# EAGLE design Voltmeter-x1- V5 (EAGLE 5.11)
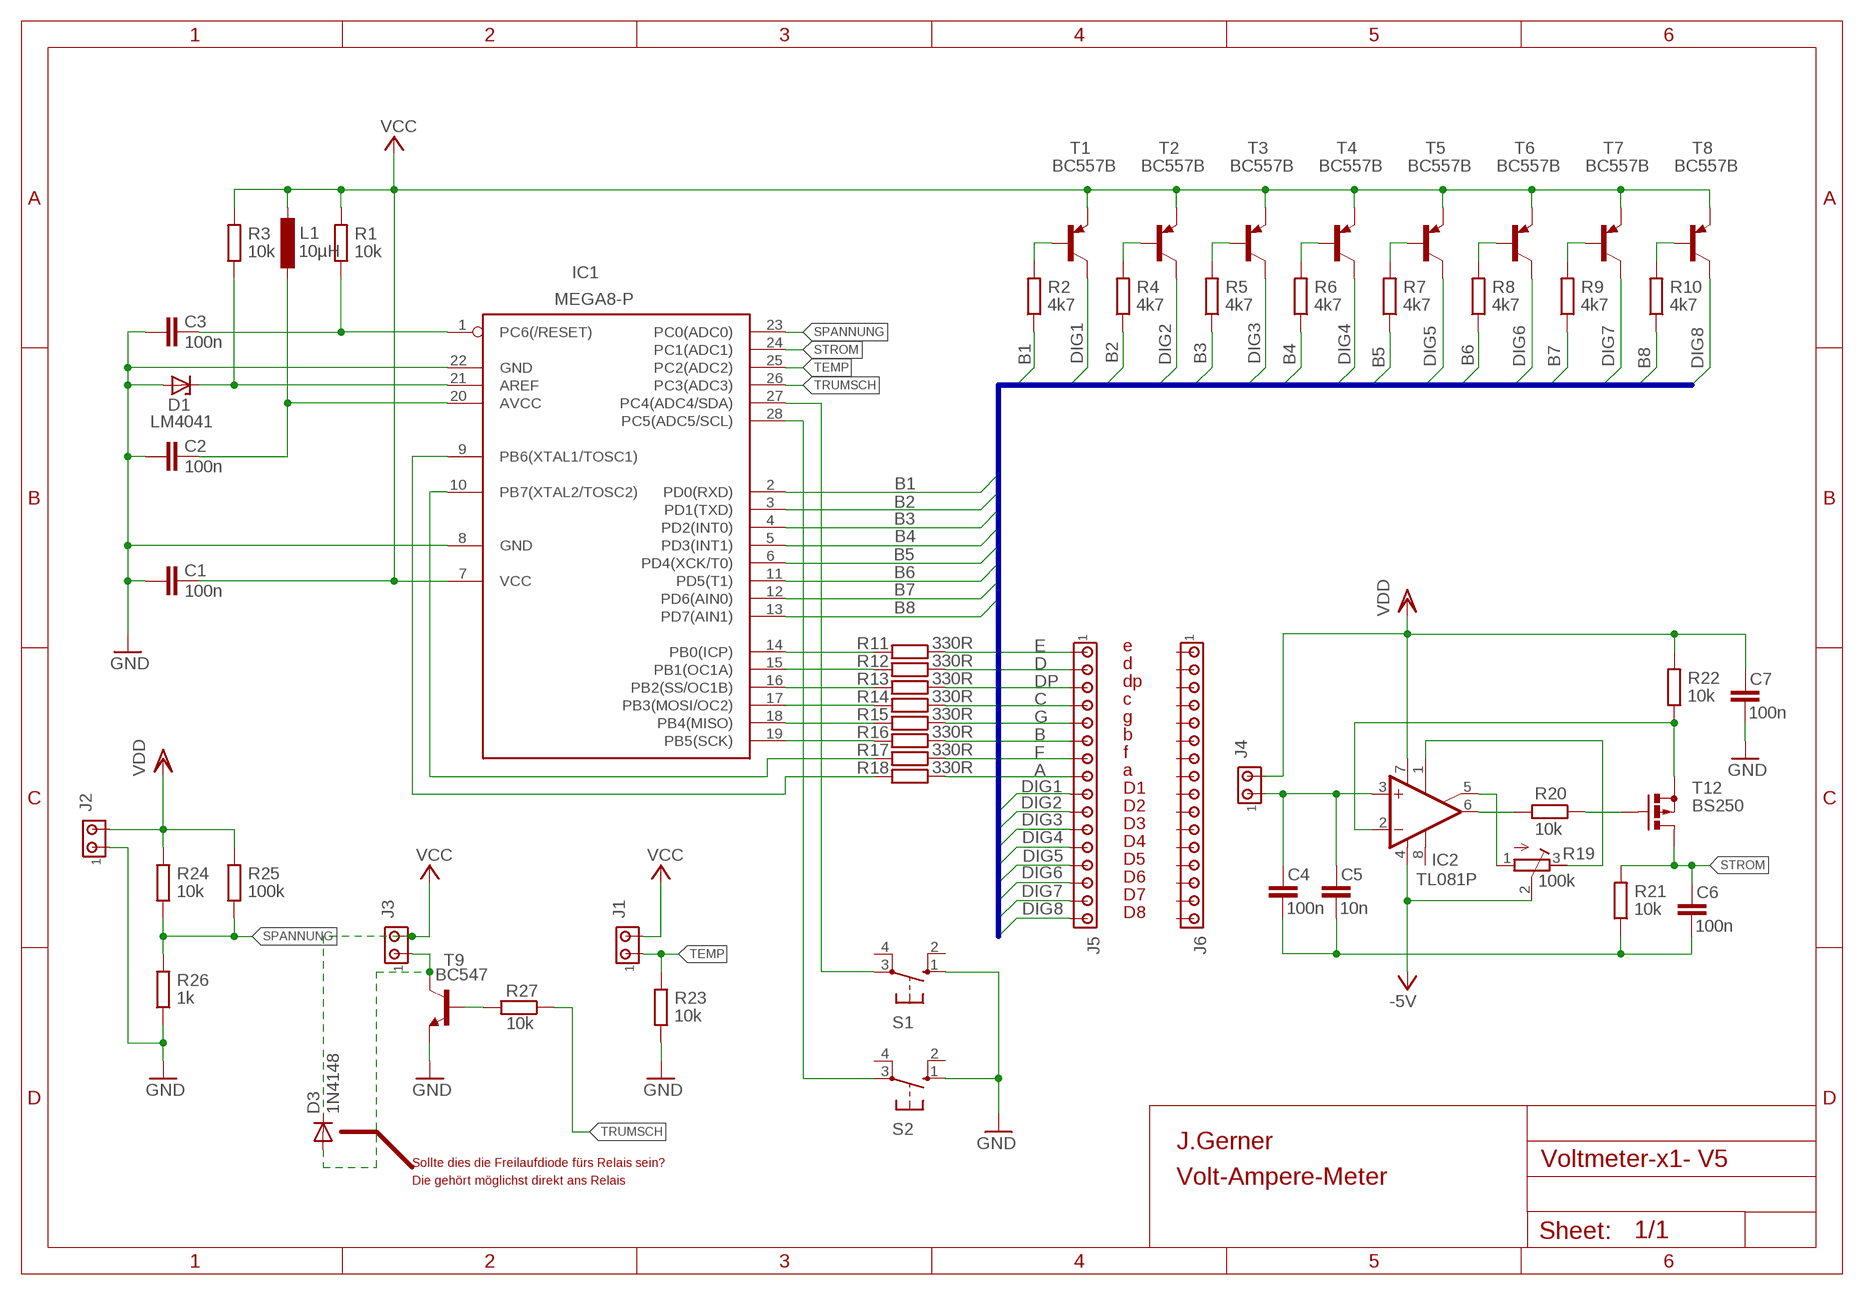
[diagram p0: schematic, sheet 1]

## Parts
C1  100n  C-EUC0805K  [C0805K]
C2  100n  C-EUC0805K  [C0805K]
C3  100n  C-EUC0805K  [C0805K]
C4  100n  C-EUC0805K  [C0805K]
C5  10n  C-EUC0805K  [C0805K]
C6  100n  C-EUC0805K  [C0805K]
C7  100n  C-EUC0805K  [C0805K]
D1  LM4041  1N4728  [DO41Z10]
D3  1N4148  1N4148DO35-7  [DO35-7]
IC1  MEGA8-P  [DIL28-3]
IC2  TL081P  [DIL08]
J1  MTA02-100  [10X02MTA]
J2  MTA02-100  [10X02MTA]
J3  MTA02-100  [10X02MTA]
J4  MTA02-100  [10X02MTA]
J5  MTA16-156  [1X16MTA]
J6  MTA16-156  [1X16MTA]
L1  10µH  L-EU0204V  [0204V]
R1  10k  R-EU_0204/2V  [0204V]
R2  4k7  R-EU_0204/2V  [0204V]
R3  10k  R-EU_0204/2V  [0204V]
R4  4k7  R-EU_0204/2V  [0204V]
R5  4k7  R-EU_0204/2V  [0204V]
R6  4k7  R-EU_0204/2V  [0204V]
R7  4k7  R-EU_0204/2V  [0204V]
R8  4k7  R-EU_0204/2V  [0204V]
R9  4k7  R-EU_0204/2V  [0204V]
R10  4k7  R-EU_0204/2V  [0204V]
R11  330R  R-EU_0204/2V  [0204V]
R12  330R  R-EU_0204/2V  [0204V]
R13  330R  R-EU_0204/2V  [0204V]
R14  330R  R-EU_0204/2V  [0204V]
R15  330R  R-EU_0204/2V  [0204V]
R16  330R  R-EU_0204/2V  [0204V]
R17  330R  R-EU_0204/2V  [0204V]
R18  330R  R-EU_0204/2V  [0204V]
R19  100k  R-TRIMM3296Y  [RTRIM3296Y]
R20  10k  R-EU_0204/2V  [0204V]
R21  10k  R-EU_0204/2V  [0204V]
R22  10k  R-EU_0204/2V  [0204V]
R23  10k  R-EU_0204/2V  [0204V]
R24  10k  R-EU_0204/2V  [0204V]
R25  100k  R-EU_0204/2V  [0204V]
R26  1k  R-EU_0204/2V  [0204V]
R27  10k  R-EU_0207/10  [0207/10]
S1  10-XX  [B3F-10XX]
S2  10-XX  [B3F-10XX]
T1  BC557B  [TO92-EBC]
T2  BC557B  [TO92-EBC]
T3  BC557B  [TO92-EBC]
T4  BC557B  [TO92-EBC]
T5  BC557B  [TO92-EBC]
T6  BC557B  [TO92-EBC]
T7  BC557B  [TO92-EBC]
T8  BC557B  [TO92-EBC]
T9  BC547  BC547B-NPN-TO92-CBE  [TO92-CBE]
T12  BS250  [SOT54E]

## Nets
-5V: IC2.4(V-) R19.2(S)
A: J5.8 R18.1
B: J5.6 R16.1
B1: IC1.2(PD0(RXD)) R2.1
B2: IC1.3(PD1(TXD)) R4.1
B3: IC1.4(PD2(INT0)) R5.1
B4: IC1.5(PD3(INT1)) R6.1
B5: IC1.6(PD4(XCK/T0)) R7.1
B6: IC1.11(PD5(T1)) R8.1
B7: IC1.12(PD6(AIN0)) R9.1
B8: IC1.13(PD7(AIN1)) R10.1
C: J5.4 R14.1
D: J5.2 R12.1
DIG1: J5.9 T1.C
DIG2: J5.10 T2.C
DIG3: J5.11 T3.C
DIG4: J5.12 T4.C
DIG5: J5.13 T5.C
DIG6: J5.14 T6.C
DIG7: J5.15 T7.C
DIG8: J5.16 T8.C
DP: J5.3 R13.1
E: J5.1 R11.1
F: J5.7 R17.1
G: J5.5 R15.1
GND: C1.2 C2.2 C3.2 C7.2 D1.A IC1.8(GND) IC1.22(GND) J2.1 R23.1 R26.1 S1.1(S) S2.1(S) T9.E
N$1: C3.1 IC1.1(PC6(/RESET)) R1.1
N$2: IC1.10(PB7(XTAL2/TOSC2)) R17.2
N$3: D1.C IC1.21(AREF) R3.1
N$4: C2.1 IC1.20(AVCC) L1.2
N$5: IC1.9(PB6(XTAL1/TOSC1)) R18.2
N$6: R2.2 T1.B
N$7: R4.2 T2.B
N$8: IC1.14(PB0(ICP)) R11.2
N$9: R5.2 T3.B
N$10: IC1.15(PB1(OC1A)) R12.2
N$11: R6.2 T4.B
N$12: IC1.16(PB2(SS/OC1B)) R13.2
N$13: R7.2 T5.B
N$14: IC1.17(PB3(MOSI/OC2)) R14.2
N$15: R8.2 T6.B
N$16: IC1.18(PB4(MISO)) R15.2
N$17: IC1.19(PB5(SCK)) R16.2
N$18: R9.2 T7.B
N$19: IC2.6(OUT) R20.2
N$20: R10.2 T8.B
N$21: R20.1 T12.G
N$22: IC2.5(ON2) R19.1(A)
N$23: IC2.1(ON1) R19.3(E)
N$24: IC2.2(-IN) R22.1 T12.S
N$25: C4.1 C5.1 IC2.3(+IN) J4.1
N$26: C4.2 C5.2 C6.2 R21.1
N$27: D3.A J3.1 T9.C
N$28: R27.2 T9.B
N$30: IC1.28(PC5(ADC5/SCL)) S2.3(P)
N$31: IC1.27(PC4(ADC4/SDA)) S1.3(P)
SPANNUNG: IC1.23(PC0(ADC0)) R24.1 R25.1 R26.2
STROM: C6.1 IC1.24(PC1(ADC1)) R21.2 T12.D
TEMP: IC1.25(PC2(ADC2)) J1.1 R23.2
TRUMSCH: IC1.26(PC3(ADC3)) R27.1
VCC: C1.1 D3.C IC1.7(VCC) J1.2 J3.2 L1.1 R1.2 R3.2 T1.E T2.E T3.E T4.E T5.E T6.E T7.E T8.E
VDD: C7.1 IC2.7(V+) J2.2 J4.2 R22.2 R24.2 R25.2
Unconnected: IC2.8(OPT) J6.1 J6.2 J6.3 J6.4 J6.5 J6.6 J6.7 J6.8 J6.9 J6.10 J6.11 J6.12 J6.13 J6.14 J6.15 J6.16 S1.2(S1) S1.4(P1) S2.2(S1) S2.4(P1)

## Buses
B[1..8],DIG[1..8]

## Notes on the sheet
- e
- d
- dp
- c
- g
- b
- f
- a
- D1
- D2
- D3
- D4
- D5
- D6
- D7
- D8
- J.Gerner
- Sollte dies die Freilaufdiode fürs Relais sein?
- Die gehört möglichst direkt ans Relais | Volt-Ampere-Meter

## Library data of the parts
C1-C7 = rcl:C-EU: CAPACITOR, European symbol
D1 = diode:1N4728: Z DIODE
D3 = diode:1N4148: DIODE
IC1 = atmel:MEGA8-P: MICROCONTROLLER 8 Kbytes FLASH, 1 kbytes SRAM, 512 bytes EEPROM, USART, 4-channel 10 bit ADC, 2-channel 8 bit ADC Pin compatible with Atmega48, ATMega88, ATMega168 Source: avr.lbr; OC_FARNELL: unknown; OC_NEWARK: unknown
IC2 = burr-brown-JP:TL081: OP AMP
J1-J4 = con-amp:MTA02-100: AMP connector; OC_FARNELL: unknown; OC_NEWARK: unknown
J5 J6 = con-amp:MTA16-156: AMP connector; OC_FARNELL: unknown; OC_NEWARK: unknown
L1 = rcl:L-EU: INDUCTOR, European symbol
R1-R18 R20-R27 = rcl:R-EU_: RESISTOR, European symbol
R19 = rcl:R-TRIMM: Trimm resistor
S1 S2 = switch-omron:10-XX: OMRON SWITCH; MPN: B3F-1000; OC_FARNELL: 176432; OC_NEWARK: 36M3542
T1-T8 = transistor-pnp:BC557*: PNP Transistror
T9 = transistor:*-NPN-: NPN Transistror BF959 corrected 2008.03.06
T12 = transistor-small-signal:BS250: P-CHANNEL MOS FET

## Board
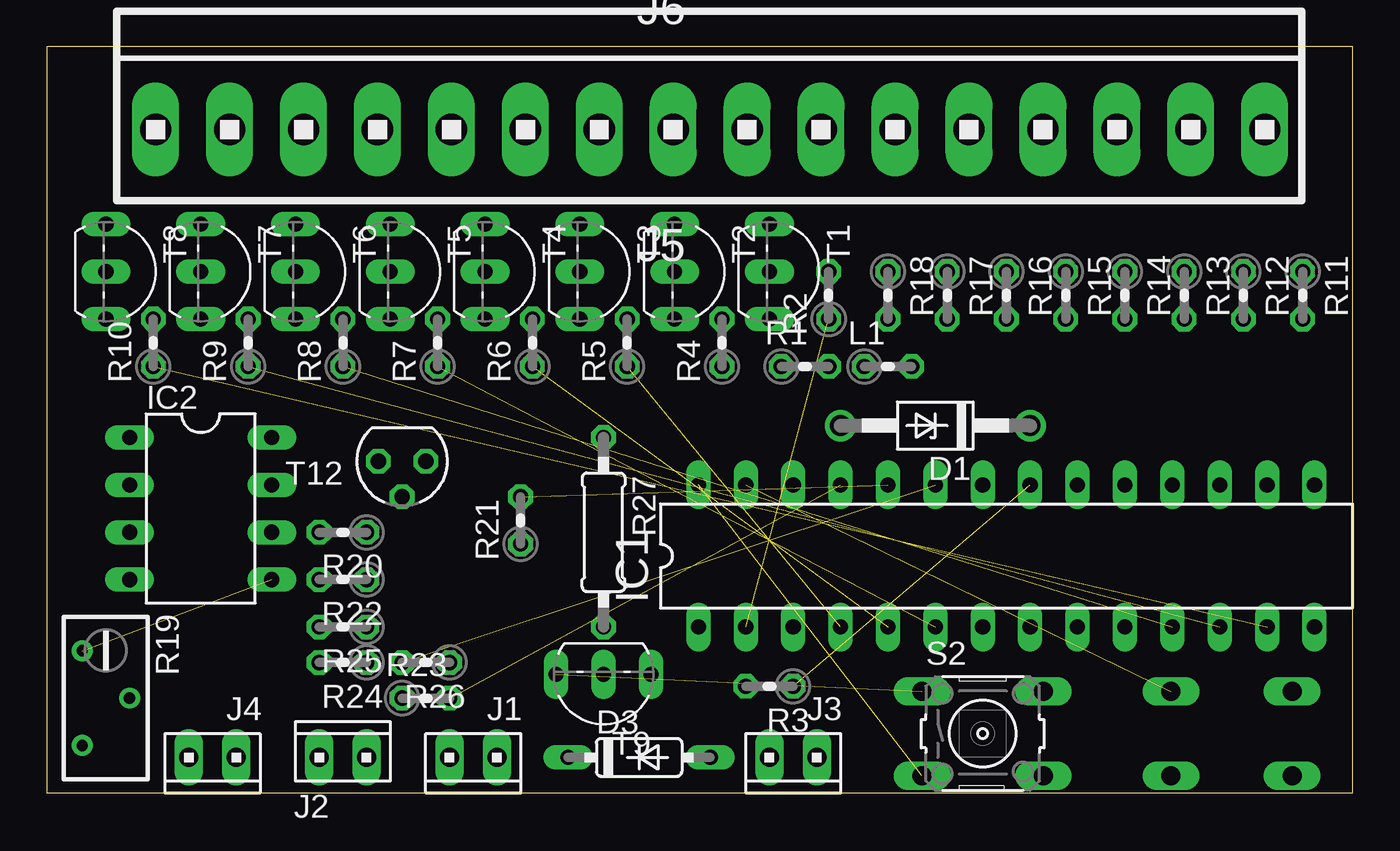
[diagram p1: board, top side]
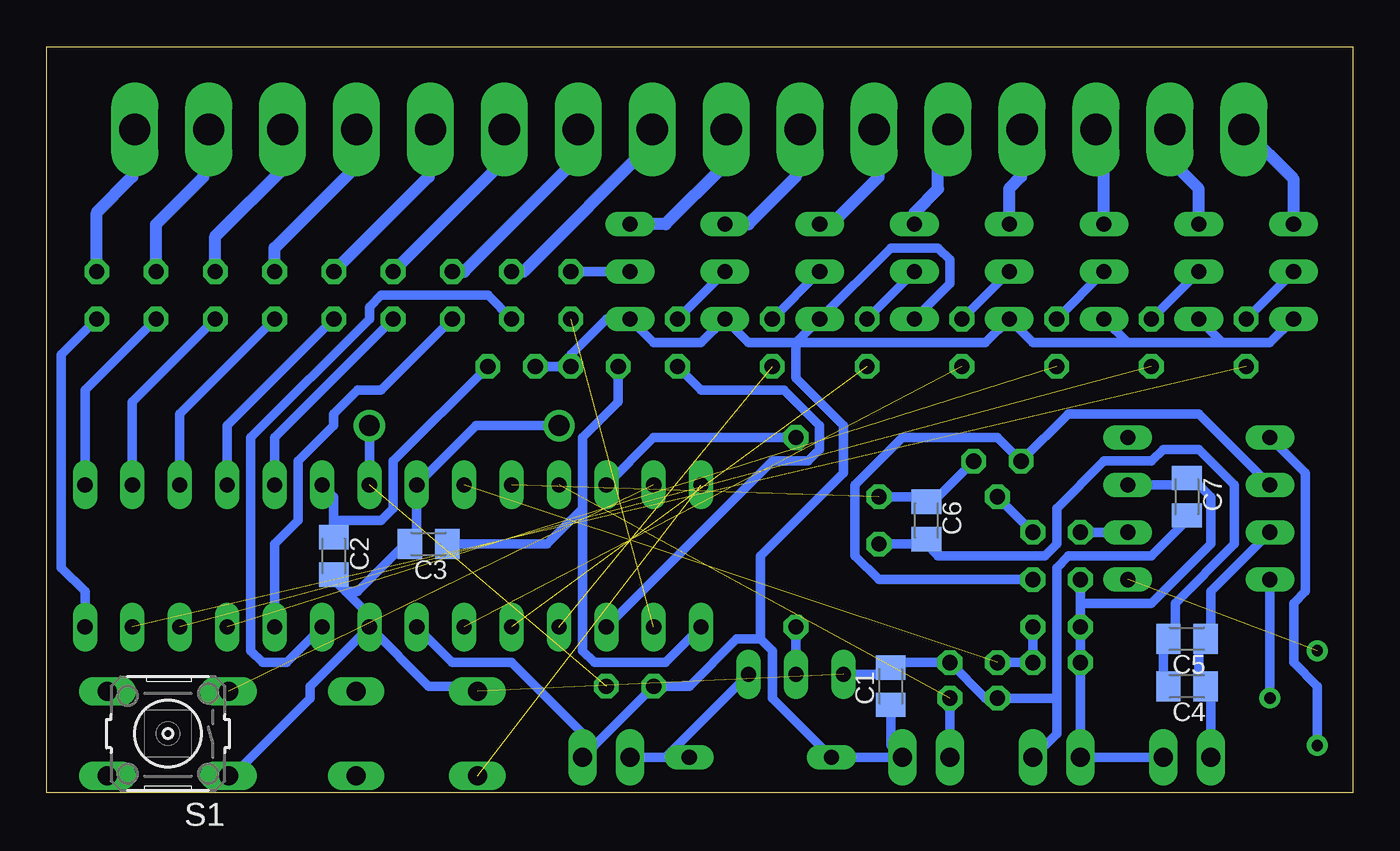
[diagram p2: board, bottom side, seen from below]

Size 70 x 40 mm. Coordinates in mm from the lower left corner, seen from the top.
Outline: 0,0 70,0 70,40 0,40 0,0
Copper layers (1*16): Top 0.035mm / dielectric 1.5mm / Bottom 0.035mm
Design rules "default *": minimum track width 20mil, minimum drill 24mil, track to track 8mil, track to pad 8mil, pad to pad 8mil, via to via 8mil, smd to smd 8mil, copper to edge 40mil, drill to drill 8mil, minimum pad ring 10mil, minimum via ring 8mil, stop-mask expansion 4mil, vias tented up to drill 0mil, thermal gap 10mil

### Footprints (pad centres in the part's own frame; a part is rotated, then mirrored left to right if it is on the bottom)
C0805K = smd 1.3 x 1.6: 1 -1,0; 2 1,0
DO41Z10 = drill 1.118 round: A 5.08,0; C -5.08,0
DO35-7 = drill 0.813 long: A 3.81,0; C -3.81,0
DIL28-3 = drill 0.813 long: 1 -16.51,-3.81; 2 -13.97,-3.81; 3 -11.43,-3.81; 4 -8.89,-3.81; 5 -6.35,-3.81; 6 -3.81,-3.81; 7 -1.27,-3.81; 8 1.27,-3.81; 9 3.81,-3.81; 10 6.35,-3.81; 11 8.89,-3.81; 12 11.43,-3.81; 13 13.97,-3.81; 14 16.51,-3.81; 15 16.51,3.81; 16 13.97,3.81; 17 11.43,3.81; 18 8.89,3.81; 19 6.35,3.81; 20 3.81,3.81; 21 1.27,3.81; 22 -1.27,3.81; 23 -3.81,3.81; 24 -6.35,3.81; 25 -8.89,3.81; 26 -11.43,3.81; 27 -13.97,3.81; 28 -16.51,3.81
DIL08 = drill 0.813 long: 1 -3.81,-3.81; 2 -1.27,-3.81; 3 1.27,-3.81; 4 3.81,-3.81; 5 3.81,3.81; 6 1.27,3.81; 7 -1.27,3.81; 8 -3.81,3.81
10X02MTA = drill 1.016 long: 1 1.27,0; 2 -1.27,0
1X16MTA = drill 1.676 long: 1 29.718,0; 2 25.756,0; 3 21.793,0; 4 17.831,0; 5 13.868,0; 6 9.906,0; 7 5.944,0; 8 1.981,0; 9 -1.981,0; 10 -5.944,0; 11 -9.906,0; 12 -13.868,0; 13 -17.831,0; 14 -21.793,0; 15 -25.756,0; 16 -29.718,0
0204V = drill 0.813 octagon: 1 -1.27,0; 2 1.27,0
RTRIM3296Y = drill 0.61 round: 1 1.27,-2.54; 2 -1.27,0; 3 1.27,2.54
0207/10 = drill 0.813 octagon: 1 -5.08,0; 2 5.08,0
B3F-10XX = drill 1.016 long: 1 -3.251,2.261; 2 3.251,2.261; 3 -3.251,-2.261; 4 3.251,-2.261
TO92-EBC = drill 0.813 long: B 0,-1.27; C -2.54,-1.27; E 2.54,-1.27
TO92-CBE = drill 0.813 long: B 0,0; C -2.54,0; E 2.54,0
SOT54E = drill 0.813 octagon: D -1.27,0; G 0,1.905; S 1.27,0

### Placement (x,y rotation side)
C1  24.77,5.71 90 bottom
C2  54.61,12.7 270 bottom
C3  49.53,13.34 180 bottom
C4  8.89,5.71 180 bottom
C5  8.89,8.26 180 bottom
C6  22.86,14.61 270 bottom
C7  8.89,15.88 270 bottom
D1  47.62,19.68 180 top
D3  31.75,1.91 0 top
IC1  51.44,12.7 0 top
IC2  8.26,15.24 270 top
J1  22.86,1.91 180 top
J2  15.88,1.91 0 top
J3  40.01,1.91 180 top
J4  8.89,1.91 180 top
J5  35.56,35.56 0 top
J6  not placed on the board
L1  45.09,22.86 0 top
R1  40.64,22.86 0 top
R2  41.91,26.67 90 top
R3  38.73,5.71 180 top
R4  36.2,24.13 90 top
R5  31.11,24.13 90 top
R6  26.04,24.13 90 top
R7  20.95,24.13 90 top
R8  15.88,24.13 90 top
R9  10.79,24.13 90 top
R10  5.71,24.13 90 top
R11  67.31,26.67 270 top
R12  64.14,26.67 270 top
R13  60.96,26.67 270 top
R14  57.78,26.67 270 top
R15  54.61,26.67 270 top
R16  51.44,26.67 270 top
R17  48.26,26.67 270 top
R18  45.09,26.67 270 top
R19  3.17,5.08 180 top
R20  15.88,13.97 180 top
R21  25.4,14.61 90 top
R22  15.88,11.43 180 top
R23  20.32,5.08 0 top
R24  15.88,6.99 180 top
R25  15.88,8.89 180 top
R26  20.32,6.99 180 top
R27  29.84,13.97 270 top
S1  63.5,3.17 180 bottom
S2  50.16,3.17 0 top
T1  40.01,27.94 270 top
T2  34.92,27.94 270 top
T3  29.84,27.94 270 top
T4  24.77,27.94 270 top
T5  19.68,27.94 270 top
T6  14.61,27.94 270 top
T7  9.53,27.94 270 top
T8  4.45,27.94 270 top
T9  29.84,6.35 180 top
T12  19.05,17.78 180 top

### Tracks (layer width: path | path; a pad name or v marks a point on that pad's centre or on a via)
-5V
  Bottom 0.508: R19.2 IC2.4
A
  Bottom 0.635: R18.1 44.45,27.94 37.47,34.92 37.47,35.48 J5.8
B
  Bottom 0.635: R16.1 45.72,33.66 45.72,35.31 J5.6
B1  (1 unrouted)
B2
  Bottom 0.508: IC1.3 31.11,17.78 29.21,17.78 28.57,18.41 28.57,19.68 30.48,21.59 34.92,21.59 R4.1
B3  (1 unrouted)
B4  (1 unrouted)
B5  (1 unrouted)
B6  (1 unrouted)
B7  (1 unrouted)
B8  (1 unrouted)
C
  Bottom 0.635: R14.1 57.78,29.21 53.34,33.66 53.34,35.51 J5.4
D
  Bottom 0.635: R12.1 64.14,30.48 61.59,33.02 61.59,35.28 J5.2
DIG1
  Bottom 0.635: T1.C 36.83,30.48 33.66,33.66 33.66,35.48 J5.9
DIG2
  Bottom 0.635: T2.C 32.38,30.48 29.84,33.02 29.84,35.33 J5.10
DIG3
  Bottom 0.635: T3.C 27.94,30.48 25.4,33.02 25.4,35.31 J5.11
DIG4
  Bottom 0.635: T4.C 23.5,31.11 22.23,32.38 22.23,35.03 J5.12
DIG5
  Bottom 0.635: T5.C 18.41,32.38 17.78,33.02 17.78,35.51 J5.13
DIG6
  Bottom 0.635: T6.C 13.34,35.13 J5.14
DIG7
  Bottom 0.635: T7.C 8.26,32.38 9.53,33.66 9.53,35.28 J5.15
DIG8
  Bottom 0.635: T8.C 3.17,32.89 J5.16
DP
  Bottom 0.635: R13.1 60.96,29.84 57.15,33.66 57.15,35.36 J5.3
E
  Bottom 0.635: R11.1 67.31,31.11 65.41,33.02 65.41,35.43 J5.1
F
  Bottom 0.635: R17.1 47.62,27.94 41.27,34.29 41.27,35.33 J5.7
G
  Bottom 0.635: R15.1 49.53,33.02 49.53,35.46 J5.5
GND  (1 unrouted)
  Bottom 0.508: D1.A 46.99,19.68 IC1.22 50.16,13.34 C3.2 50.8,13.34 53.34,10.79 53.98,10.79 | T9.E 24.77,6.35 C1.2 24.77,6.99 R26.1 19.68,5.08 R23.1 15.88,5.08 | 15.88,5.08 15.88,3.17 J2.1 | 15.88,5.08 15.88,12.06 15.24,12.7 10.79,12.7 8.89,14.61 C7.2 | 53.98,10.79 52.7,9.53 IC1.8 | 53.98,10.79 54.61,11.43 C2.2 | IC1.8 49.53,5.71 46.99,5.71 S2.1 | IC1.8 55.88,5.71 55.88,5.08 59.69,1.27 S1.1
N$1
  Bottom 0.508: 41.27,15.24 43.18,13.34 C3.1 | 41.27,15.24 41.27,19.05 39.37,20.95 R1.1 | IC1.1 36.83,6.99 40.64,6.99 41.27,7.62 41.27,15.24
N$2
  Bottom 0.508: IC1.10 57.78,13.34 56.52,14.61 56.52,17.78 54.61,19.68 54.61,20.32 53.34,21.59 52.07,21.59 R17.2
N$3  (1 unrouted)
  Bottom 0.508: IC1.21 D1.C
N$4
  Bottom 0.508: 54.61,14.61 54.61,15.88 IC1.20 | 54.61,14.61 C2.1 | L1.2 51.44,17.78 51.44,15.24 52.07,14.61 54.61,14.61
N$5
  Bottom 0.508: IC1.9 57.15,6.99 58.42,6.99 59.05,7.62 59.05,19.05 52.7,25.4 52.7,26.04 52.07,26.67 46.35,26.67 R18.2
N$6
  Bottom 0.508: T1.B R2.2
N$7
  Bottom 0.508: R4.2 T2.B
N$8
  Bottom 0.508: IC1.14 67.94,10.79 69.22,12.06 69.22,23.5 R11.2
N$9
  Bottom 0.508: R5.2 T3.B
N$10
  Bottom 0.508: IC1.15 67.94,21.59 R12.2
N$11
  Bottom 0.508: R6.2 T4.B
N$12
  Bottom 0.508: IC1.16 65.41,20.95 R13.2
N$13
  Bottom 0.508: R7.2 T5.B
N$14
  Bottom 0.508: IC1.17 62.87,20.32 R14.2
N$15
  Bottom 0.508: R8.2 T6.B
N$16
  Bottom 0.508: IC1.18 60.33,19.68 R15.2
N$17
  Bottom 0.508: IC1.19 57.78,19.05 R16.2
N$18
  Bottom 0.508: R9.2 T7.B
N$19
  Bottom 0.508: IC2.6 R20.2
N$20
  Bottom 0.508: R10.2 T8.B
N$21
  Bottom 0.508: R20.1 T12.G
N$22  (1 unrouted)
N$23
  Bottom 0.508: R19.3 1.91,5.71 3.17,6.99 3.17,10.16 2.54,10.79 2.54,17.14 IC2.1
N$24
  Bottom 0.508: R22.1 25.4,11.43 26.67,12.7 26.67,16.51 24.13,19.05 19.05,19.05 T12.S 15.24,20.32 8.26,20.32 IC2.2
N$25
  Bottom 0.508: J4.1 7.62,5.71 C4.1 8.26,5.71 8.26,8.26 C5.1 7.62,8.26 7.62,10.79 IC2.3
N$26
  Bottom 0.508: C4.2 10.16,5.71 10.16,8.26 C5.2 9.53,8.26 9.53,10.16 6.35,13.34 6.35,16.51 8.26,18.41 10.16,18.41 10.79,17.78 13.34,17.78 15.88,15.24 15.88,13.34 16.51,12.7 22.23,12.7 22.86,13.34 | 22.86,13.34 R21.1 | 22.86,13.34 C6.2
N$27
  Bottom 0.508: 36.83,1.91 J3.1 | 36.83,1.91 T9.C | D3.A 36.83,1.91
N$28
  Bottom 0.508: T9.B R27.2
N$30  (1 unrouted)
N$31  (1 unrouted)
SPANNUNG  (1 unrouted)
  Bottom 0.508: R25.1 R24.1 R26.2
STROM  (1 unrouted)
  Bottom 0.508: R21.2 22.86,15.88 C6.1 22.86,15.24 T12.D
TEMP  (1 unrouted)
  Bottom 0.508: J1.1 R23.2
TRUMSCH
  Bottom 0.508: R27.1 37.47,19.05 IC1.26
VCC
  Bottom 0.508: 29.84,24.13 T3.E 24.77,29.21 22.23,29.21 21.59,28.57 21.59,27.3 T4.E | 29.84,24.13 32.38,24.13 T2.E 34.92,24.13 37.47,24.13 T1.E 40.01,25.4 41.91,23.5 R1.2 L1.1 | T8.E 4.45,24.13 6.99,24.13 | 6.99,24.13 T7.E | 12.06,24.13 T6.E | 12.06,24.13 6.99,24.13 | 12.06,24.13 17.14,24.13 T5.E 19.68,24.13 29.84,24.13 | C1.1 24.77,2.54 J1.2 D3.C 31.11,5.08 31.11,7.62 31.75,8.26 | 40.64,2.54 R3.2 35.56,5.71 33.02,8.26 31.75,8.26 | IC1.7 48.26,6.99 45.09,6.99 40.64,2.54 | 40.64,2.54 J3.2 | 29.84,24.13 29.84,22.23 27.3,19.68 27.3,17.14 31.75,12.7 31.75,8.26
VDD
  Bottom 0.508: 8.26,16.51 IC2.7 | J4.2 J2.2 R24.2 R25.2 14.61,10.16 | 14.61,10.16 R22.2 | 8.26,16.51 7.62,15.88 7.62,13.34 10.79,10.16 14.61,10.16 | 8.26,16.51 C7.1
